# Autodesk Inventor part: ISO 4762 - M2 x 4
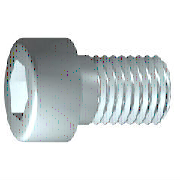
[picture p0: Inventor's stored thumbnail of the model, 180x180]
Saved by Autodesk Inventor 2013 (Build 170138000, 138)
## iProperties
IsCustomPart: 0
Created: 2012-02
Part Number: ISO 4762 - M2 x 4
Material: Edelstahl, 440C
Description: Innensechskantschraube
Document SubType Name: Modeling
Standard: ISO 4762
Designer: rYan
Standard Revision: 1998
Standards Organization: DIN
Language: de-DE
Size Designation: M2 x 4
Categories: <MemberInstance><Categories><Category DisplayName="Verbindungselemente" InternalName="e4da775c-781d-43d5-af7c-5136215cf5a6" Mnemonic="FSTN"><Category DisplayNam
Density: 7.75 g/cm^3
Mass: 0.253101 g
Surface Area: 0.751281 cm^2
Volume: 0.0326582 cm^3
Author: rYan
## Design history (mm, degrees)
sketch "Skizze1"
  geometry: L1 (-0.5, 0)-(4, 0); L2 (4, 0)-(4, 1); L3 (4, 1)-(1, 1); L4 (1, 1)-(0.755, 1); L5 (0.755, 1)-(0, 1); L6 (0, 1)-(0, 1.9); L7 (0, 1.9)-(-2, 1.9); L8 (-2, 1.9)-(-2, 0.866); L9 (-2, 0.866)-(-1, 0.866); L10 (-1, 0.866)-(-0.5, 0); L11 (-3.2, 0)-(5.2, 0) reference; L12 (0, -0.38)-(0, 2.28) reference; L13 (1, 1)-(0, 1)
  constraints: 22 end point, 6 parallel, 2 collinear, 2 perpendicular, 1 horizontal, 1 point on line
  dimensions: "d1" = 3 distance from line of L3.end L2 (= GEL); "d2" = 0.24548 distance of L4.end L3.end (computed from GAL); "d3" = 2 distance between parallel lines of L8 L6 (= KOH); "d4" = 1 distance of L8.end L9.end (= INTI); "d5" = 60 deg angle of L10 L1; "d6" = 2 diameter of L3 L1 (= GD); "d7" = 2 diameter of L5 L1 (= BDM); "d8" = 1.73205 diameter of L9 L1 (= 1.1547 x SW); "d9" = 3.8 diameter of L7 L1 (= KOD); "d26" = 4 distance between parallel lines of L12 L2 (= NLG)
revolve "Körper" sketch "Skizze1" stored, may be unused: angle "d10" = 90 deg
sketch "Skizze2"
  geometry: L1 (0, -2.66)-(0, 2.66) reference; L2 (-2.66, 0)-(2.66, 0) reference; L3 (0.866, 0)-(0.433, -0.75); L4 (0.433, -0.75)-(-0.433, -0.75); L5 (-0.433, -0.75)-(-0.866, 0); L6 (-0.866, 0)-(-0.433, 0.75); L7 (-0.433, 0.75)-(0.433, 0.75); L8 (0.433, 0.75)-(0.866, 0); 2 further points
  constraints: 12 end point, 1 coincident, 1 horizontal alignment, 1 point on line, 12 other
extrude "Loch" join sketch "Skizze2" stored distance "d11" = 10; taper "d12" = 0 deg
workplane "Work Plane1"
fillet "Fillet2" dims "d30" = 0.1 (= R)
body "Solid1"
fillet "Rundung1" dims "d17" = 0.2 (= RR)
feature "Gewinde" dims "d13" = 3 (= GEL), "d14" = 0
chamfer "Fase1" distance "d15" = 0.24538 (= -0.5 x SPD + 0.5 x GD); stored, may be unused: second distance "d16" = 0.24538 (= GUL), angle "d27" = 45 deg
other parameters: "GD" = 2 [user parameter; used in 2 equation terms], "NLG" = 4 [user parameter; used in 1 equation term], "GEL" = 3 [user parameter; used in 2 equation terms], "KOD" = 3.8 [user parameter; used in 1 equation term], "KOH" = 2 [user parameter; used in 1 equation term], "INTI" = 1 [user parameter; used in 1 equation term], "GAL" = 0.24538 (= 0.61345 x PTC) [user parameter; used in 1 equation term], "GUL" = 0.24538 (= 0.61345 x PTC) [user parameter; used in 1 equation term], "BDM" = 2 (= NND) [user parameter; used in 1 equation term], "SW" = 1.5 [user parameter; used in 2 equation terms], "RR" = 0.2 [user parameter; used in 1 equation term], "SPD" = 1.50924 (= NND - 1.2269 x PTC) [user parameter; used in 1 equation term], "d19" = 0, "d28" = 0, "d29" = 0, "R" = 0.1 [user parameter; used in 1 equation term], "TOA" = 30 deg [user parameter], "GD1" = 1.50924 (= THREADDIA - 1.2269 x PTC) [user parameter], "THREADDIA" = 2 [user parameter; used in 1 equation term], "FAWI" = 45 deg [user parameter], "TPU" = 25 (computed from PTC) [user parameter], "PTC" = 0.4 [user parameter; used in 5 equation terms], "NND" = 2 [user parameter; used in 2 equation terms], "E0" = 1.7325 (= 1.155 x SW) [user parameter]
